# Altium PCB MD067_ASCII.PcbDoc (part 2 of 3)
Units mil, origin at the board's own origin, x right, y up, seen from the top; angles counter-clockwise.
Board outline 3650 x 4750 mil, 4 copper layers (Top Layer, GND Layer, Power Layer, Bottom Layer), stack 58.4 mil thick; 234 components, 118 nets, 586 pads, 972 vias.
Unrouted connection lines stored in the file: 42.
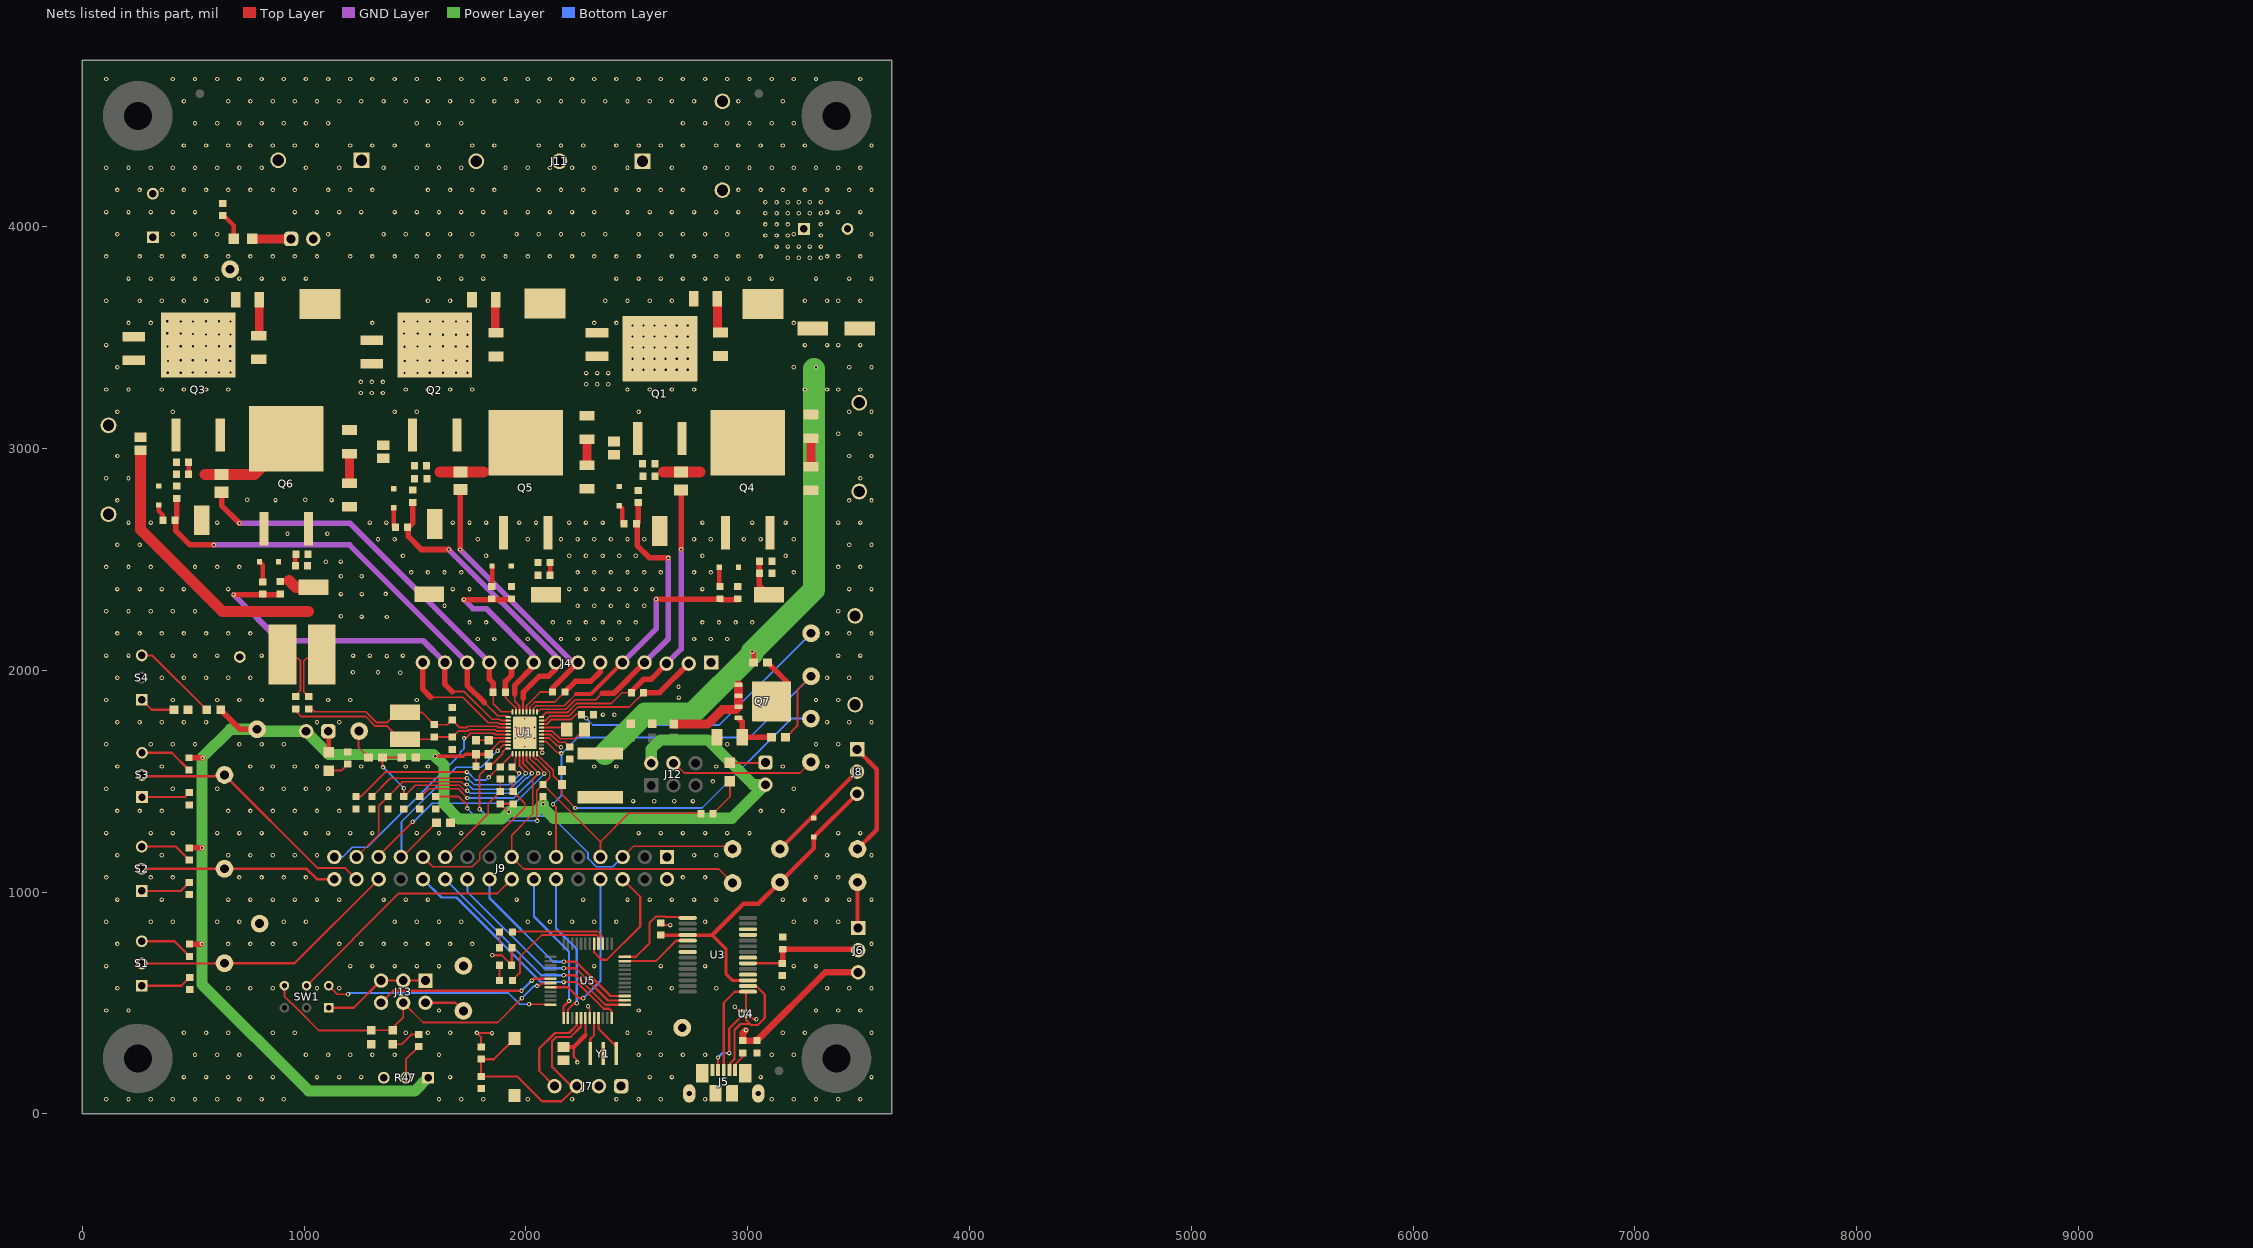
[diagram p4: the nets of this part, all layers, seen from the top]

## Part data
C1 C37: library part CMP-0006872-5, "CAP, CERM, 10 uF, 6.3 V, +/- 20%, X5R, 0603"
C2 C38: library part CMP-0085846-1, "CAP, CERM, 0.1 µF, 6.3 V,+/- 10%, X5R, 0603"
C3: library part CMP-0008374-1, "CAP, CERM, 0.47 uF, 100 V, +/- 10%, X7R, 0805"
C4: library part CMP-0007302-2, "CAP, CERM, 1 uF, 6.3 V, +/- 10%, X5R, 0603"
C5: library part CMP-0007007-5, "CAP, CERM, 10 uF, 25 V, +/- 20%, X5R, 0603"
C6: library part CMP-0009304-2, "CAP, CERM, 10 uF, 100 V, +/- 20%, X7R, 2220"
C7: library part CMP-0007470-5, "CAP, CERM, 0.1 uF, 100 V, +/- 10%, X7R, 0603"
C8 C9 C10: library part CMP-0007006-5, "CAP, CERM, 1 uF, 25 V, +/- 10%, X5R, 0603"
C11 C16 C47: library part CMP-0006815-4, "CAP, CERM, 0.1 uF, 10 V, +/- 10%, X7R, 0603"
C12 C13 C14 C24 C25 C26: library part CMP-0008756-2, "CAP CER 3900PF 100V X7R 1206"
C15 C17 C19 C27 C28 C29: library part CMP-0007441-5, "CAP, CERM, 2000 pF, 50 V, +/- 10%, X7R, 0603"
C18 C20 C44: library part CMP-0009182-2, "CAP, CERM, 4.7 uF, 100 V, +/- 10%, X7S, 1210"
C21 C22 C23: library part CMP-0007542-2, "CAP, CERM, 0.01 uF, 100 V, +/- 5%, X7R, 0805"
C30 C32: library part CMP-0006740-4, "CAP, CERM, 330 pF, 100 V, +/- 10%, X7R, 0603"
C31: library part CMP-0006998-4, "CAP, CERM, 0.01 uF, 50 V, +/- 5%, C0G/NP0, 0603"
C33: library part CMP-0011397-2, "CAP, AL, 10 uF, 80 V, +/- 20%, 2.4 ohm, SMD"
C34 C35: library part CMP-0009875-2, "CAP, AL, 390 uF, 100 V, +/- 20%, 0.026 ohm, TH"
C36: library part CMP-0006812-1, "CAP, CERM, 100 pF, 10 V, +/- 10%, X7R, 0603"
C39: library part CMP-0082630-1, "CAP, CERM, 2000 pF, 50 V,+/- 5%, C0G/NP0, 1206"
C46: library part CMP-0007498-4, "CAP, CERM, 4.7 uF, 10 V, +/- 20%, X7R, 0603"
C48: library part CMP-0006826-4, "CAP, CERM, 1000 pF, 16 V, +/- 10%, X7R, 0603"
C49: library part CMP-0007696-2, "CAP, CERM, 1 uF, 50 V, +/- 10%, X7R, 0805"
D1 D3: library part CMP-0002888-2, "LED, Green, SMD"
D2: library part CMP-0002829-3, "LED, Red, SMD"
D4: library part CMP-0028882-2, "Diode, Schottky, 40 V, 0.75 A, AEC-Q101, SOD-323"
D5 D6 D7 D8 D9 D10: library part CMP-0076911-2, "Diode, Switching, 75 V, 0.25 A, SOD-323"
D13 D14: library part CMP-0078131-2, "LED, Red, SMD"
FID1 FID2 FID3: library part CMP-0077181-1, "Fiducial mark.  There is nothing to buy or mount."
H1 H2 H3 H4: "Standoff, Hex, 1\"L #4-40 Nylon"
H5 H6 H7 H8: "Machine Screw, Round, #4-40 x 1/4, Nylon, Philips panhead"
J1 J2 J3: library part CMP-0075405-3, "Header, 100mil, 2x1, Gold, TH"
J4: library part CMP-0075428-1, "Header, 100mil, 14x1, Gold, TH"
J5: library part CMP-0055311-1, "Receptacle, USB 2.0, Micro B, 5 Position, R/A, SMT"
J6 J8: library part CMP-0002334-1, "Header, 100mil, 3x1, Gold, TH"
J7: library part CMP-0075409-2, "Header, 100mil, 4x1, Gold, TH"
J9: library part CMP-0075429-1, "Header, 100mil, 16x2, Gold, TH"
J10: library part CMP-0055527-1, "Terminal Block, 9.52mm, 2x1, R/A, TH"
J11: library part CMP-0055528-1, "Terminal Block, 9.52mm, 3x1, R/A, TH"
J12 J13: library part CMP-0075406-2, "Header, 100mil, 3x2, Gold, TH"
L1: library part CMP-0084877-1, "Inductor, Ferrite Bead, Ferrite, 3 A, 120 ohm, AEC-Q200 Grade 1, SMD"
Logo1: library part CMP-0074844-1
Logo2: library part CMP-0074838-1, "Texas Instrument Corporate Signature"
Logo3: library part CMP-0074847-1, "FCC_disclaimer"
Logo4: library part CMP-0074769-1
LOGO5 LOGO6: library part CMP-0074837-1, "IEC 61010-1 Hot Surface Warning"
NT1 NT2 NT3: library part CMP-0078142-2, "Single point connection between nets."
Q1 Q2 Q3 Q4 Q5 Q6: library part CMP-0092295-1, "MOSFET 60-V, N channel NexFET power MOSFET, single D2PAK, 1.6 mOhm 3-DDPAK/TO-263 -55 to 175"
Q7: library part CMP-0000817-1, "MOSFET, N-CH, 60 V, 50 A, DQJ0008A (VSONP-8)"
R1 R2 R3 R4 R5 R6 R11 R12 R43 R45 R46 R49 R55 R56 R57: library part CMP-0025874-4, "RES, 0, 5%, 0.1 W, AEC-Q200 Grade 0, 0603"
R7 R8 R9 R10: library part CMP-0025830-4, "RES, 5.1 k, 5%, 0.1 W, AEC-Q200 Grade 0, 0603"
R13 R14: library part CMP-0025941-5, "RES, 820, 5%, 0.1 W, 0603"
R15: library part CMP-0023463-3, "RES, 2.00 k, 0.1%, 0.1 W, 0603"
R16: library part CMP-0025925-5, "RES, 47 k, 5%, 0.1 W, 0603"
R17 R18: library part CMP-0025924-5, "RES, 470, 5%, 0.1 W, 0603"
R19 R20 R21 R23 R24 R48 R52 R53: library part CMP-0086251-1, "RES, 10.0 k, 0.05%, 0.1 W, AEC-Q200 Grade 0, 0603"
R22 R60 R75 R76 R77 R78: library part CMP-0025701-2, "RES, 10 k, 5%, 0.1 W, 0603"
R25 R26 R27 R40 R41 R42: library part CMP-0016763-3, "RES, 1.50, 1%, 0.25 W, AEC-Q200 Grade 0, 1206"
R28 R29 R30 R31 R32 R33 R34 R35 R36 R37 R38 R39: library part CMP-0025703-4, "RES, 10, 5%, 0.1 W, AEC-Q200 Grade 0, 0603"
R44: library part CMP-0015025-2, "RES, 0.001, 1%, 4 W, RES_2725"
R47: library part CMP-0001776-2, "Trimmer Potentiometer, 25kohm, 0.5W, TH"
R50: library part CMP-0085900-1, "RES, 1.00 M, 1%, 0.1 W, AEC-Q200 Grade 0, 0603"
R51: library part CMP-0023630-1, "RES, 100 k, 0.1%, 0.1 W, 0603"
R54: library part CMP-0024269-1, "RES, 47.0, 0.1%, 0.1 W, 0603"
S1 S2 S3 S4: library part CMP-0002155-2, "SWITCH TOGGLE SPDT 0.4VA 28V"
S5: library part CMP-0002196-2, "Switch, Tactile, SPST, 12 V, SMD"
SH-J1 SH-J2 SH-J3 SH-J4 SH-J5 SH-J6 SH-J7 SH-J8 SH-J10 SH-J11 SH-J12 SH-J13 SH-J14 SH-J15 SH-J16 SH-J17 SH-J18 SH-J19 SH-J20 SH-J21 SH-J22 SH-J23 SH-J24: library part CMP-0003623-3, "Shunt, 100mil, Gold plated, Black"
SW1: library part CMP-0002204-1, "Switch, DPDT, On-On, 0.4 VA, 28 V, TH"
TP1 TP10 TP14 TP30 TP40 TP41 TP42 TP43 TP44 TP45: library part CMP-0055137-1, "Test Point, Miniature, Red, TH"
TP2 TP3 TP4 TP5 TP26 TP31 TP32 TP33: library part CMP-0055139-1, "Test Point, Miniature, White, TH"
TP8 TP12 TP25: library part CMP-0055138-1, "Test Point, Miniature, Black, TH"
TP9 TP11 TP15 TP16 TP17 TP18 TP19 TP20 TP39: library part CMP-0055152-1, "Test Point, Miniature, SMT"
TP21 TP22 TP23 TP24: library part CMP-0075110-1, "1mm Uninsulated Shorting Plug, 10.16mm spacing, TH"
TP27 TP28 TP29: library part CMP-0055153-1, "Test Point, Compact, SMT"
U1: library part CMP-0095893-1, "High Speed Sensorless Trapezoidal Control 4.5 to 60 V Three-phase BLDC Gate Driver"
U3: library part CMP-0004774-1, "USB to Serial UART, SSOP28"
U4: library part CMP-0043115-3, "4-Channel ESD Protection Array for High-Speed Data Interfaces, DRY0006A (USON-6)"
U5: library part CMP-0089204-1, "CPU16 MSP430™ FRAM Microcontroller IC 16-Bit 24MHz 32KB (32K x 8) FRAM 48-LQFP (7x7)"
Y1: library part CMP-0084387-1, "Resonator, 4 MHz, 39 pF, AEC-Q200 Grade 1, SMD"
ZZ1: library part CMP-0003616-3
ZZ2: library part CMP-0077236-1
ZZ3: library part CMP-0077237-1
ZZ4: library part CMP-0077238-1

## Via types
v1: diameter 20, hole 10, Top Layer to Bottom Layer, tented both sides, 896 vias
v2: diameter 20, hole 10, Top Layer to Bottom Layer, 67 vias
v3: diameter 19.68, hole 7.87, Top Layer to Bottom Layer, 8 vias
v4: diameter 20, hole 10, Top Layer to Bottom Layer, tented top, 1 vias

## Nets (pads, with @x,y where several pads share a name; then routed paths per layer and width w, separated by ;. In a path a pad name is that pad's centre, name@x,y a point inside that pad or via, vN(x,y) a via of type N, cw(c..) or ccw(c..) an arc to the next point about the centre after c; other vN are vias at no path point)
3V3_MCU: C49.1 D4.1 J7.2 J8.2 R16.2 R17.2 R18.2 TP45.1 U5.6 | length 1100.8
  Top Layer w10: R16.2@1798,301.56 1798,346 v1(1779,365) 1846,365 v1(1847,364) ; v2(1848,715) 1890.56,715 R17.2@1935.56,670 1936.56,671 R18.2@1936.56,748 ; 2215.53,301.53 2215.53,257 2232,240.53 v1(2232,232) ; 2268,354 2268,432.52 U5.6@2268.16,432.68
  Top Layer w19.68: TP45.1@3145,1194 3285.31,1334.31 D4.1@3298,1334.31 3298,1348 J8.2@3493,1543
  Top Layer w20: C49.1@2168.94,301.53 2215.53,301.53 2268,354
3V3COM: C16.1 D4.2 J8.3 TP41.1 U3.4 U3.17 | length 1489.9
  Top Layer w15: C16.1@2607,805.44 2726.88,805.44 2727.35,805.91 2840.09,805.91 2902,744 2902,631 2931.82,601.18 U3.17@2999,601.18
  Top Layer w19.68: 2840.09,805.91 2981.19,947 3048,947 TP41.1@3145,1044 3298,1197 D4.2@3298,1247.69 3493,1442.69 J8.3@3493,1443
3V3EXT: J8.1 TP44.1 | length 521.9
  Top Layer w19.68: J8.1@3493,1643 3582,1554 3582,1281 TP44.1@3495,1194
5V_EXT: J6.1 TP43.1 | length 207.2
  Top Layer w7.87: J6.1@3495,841 J6.1@3498,838
  Top Layer w20: J6.1@3495,841 TP43.1@3495,1044
5V_USB: C11.1 J6.3 L1.1 TP42.1 U4.6 | length 742.8
  Top Layer w7.87: U4.6@3011.69,440.19 3024.87,427 v1(3039,427)
  Top Layer w29.53: v1(2992,377.56) 2977,362.56 L1.1@2977,330.56 C11.1@3042,330.56 3349.44,638 J6.3@3498,638 J6.3@3492,632
5VCC: C46.2 C47.1 J6.2 U3.20 | length 561.3
  Top Layer w10: U3.20@3001,678.82 C46.2@3155.74,678.82
  Top Layer w25: C46.2@3155.74,678.82 3157,680.08 C47.1@3157,742.17 3493.83,742.17 J6.2@3498,738
AVDD: C1.1 C2.1 J1.2 J2.2 J12.2 R7.1 R8.2 R9.2 R10.2 R19.2 R21.2 R24.2 R47.1 R52.2 TP10.1 U1.26 | length 6869.6
  Top Layer w7.87: 1726,1621 1726.5,1621.5 ; C1.1@1775,1621.5 1775.44,1621.5 R8.2@1775.44,1568 ; C2.1@1832.49,1621.5 1832.49,1628.49 1882.63,1678.63 U1.26@1920.2,1678.63 ; v1(1923,1362) 1920.44,1362 R10.2@1885,1397.44 R9.2@1943,1397.44 ; R7.1@2077,1430.71 2078,1429.71 v2(2078,1396)
  Top Layer w15: v1(1591,1612) 1591.32,1612.32 1717.32,1612.32 1726,1621 ; 1726.5,1621.5 C1.1@1775,1621.5 ; C1.1@1775.44,1621.5 C2.1@1832.49,1621.5
  Top Layer w25: R24.2@481,1605.56 541.44,1605.56 v1(542,1605) ; R21.2@482,1199.56 539.56,1199.56 v1(540,1200) ; R19.2@483,765.56 538.56,765.56 v1(539,766) ; R52.2@623.5,1822 711.5,1734 TP10.1@788,1734
  Power Layer w50: v1@540,1605 v1(540,1200) 540,584 1021,103 1499,103 R47.1@1559,163 ; v1@540,1607 667,1734 TP10.1@788,1734 797,1725 J1.2@1009,1725 1009,1723.06 1111.06,1621 1582,1621 v1(1591,1612) 1630,1573 1630,1397 1697,1330 1891,1330 v1(1923,1362) 1924.87,1363.87 2045.87,1363.87 v2(2078,1396) 2079.13,1394.87 2079.13,1378.24 2124.37,1333 2929,1333 J2.2@3080,1484 3023,1484 2821.29,1685.71 2606.71,1685.71 2565,1644 J12.2@2565,1581
BRAKE: J9.27 U1.34 | length 1028.6
  Top Layer w7.87: J9.27@1336,1158 1336,1164 v4(1489,1317) ; U1.34@2018.62,1623.51 2018.62,1601.44 2035.92,1584.14 2036.7,1584.14 2076.81,1544.03 2076.81,1534 v1(2083,1534)
  Bottom Layer w7.87: v4@1488,1317 v4(1489,1317) 1495,1317 1578,1400 1950.85,1400 2083,1532.15 v1(2083,1534)
BRAKE_SW: J9.28 S1.2 TP26.1 | length 1225.4
  Top Layer w10: S1.2@268,677.95 639.95,677.95 TP26.1@641,679 957,679 J9.28@1336,1058
BSTA: C8.2 J4.2 U1.9 | length 770.6
  Top Layer w7.87: U1.9@2069.8,1773.12 2086.8,1773.12 2106.98,1793.3 2193.11,1793.3 2234.07,1834.25 2465.81,1834.25 C8.2@2530.56,1899
  Top Layer w25: C8.2@2530.56,1899 2603,1899 J4.2@2734,2030
BSTB: C9.1 J4.6 U1.13 | length 446.1
  Top Layer w7.87: U1.13@2018.62,1812.49 2018.62,1834.56 2041.06,1857 2129.99,1857 C9.1@2175.12,1902.13
  Top Layer w25: C9.1@2175.12,1902.13 2222.99,1950 2292,1950 2335,1993 J4.6@2335,2035
BSTC: C10.1 J4.10 U1.17 | length 254
  Top Layer w7.87: C10.1@1907.56,1901 1907.56,1877 1944.18,1840.38 1944.62,1840.38 1955.63,1829.37 U1.17@1955.63,1812.49
  Top Layer w25: C10.1@1907.56,1901 1907.56,1949.56 1935,1977 J4.10@1935,2035
CPH: C3.1 U1.7 | length 117.4
  Top Layer w7.87: U1.7@2069.8,1741.62 2176.38,1741.62 C3.1@2184,1734
CPL: C3.2 U1.6 | length 226.7
  Top Layer w7.87: U1.6@2069.8,1725.87 2118.92,1725.87 2154.11,1690.69 2220.69,1690.69 C3.2@2264,1734
DACOUT/SOX/SPEED_ANA: J9.15 R3.1 TP2.1 U1.33 | length 2196.4
  Top Layer w7.87: R3.1@1522,1430.36 1526.36,1430.36 1562,1466 1694,1466 v1(1736,1424) ; U1.33@2002.87,1623.51 2002.87,1590.97 2048.81,1545.03 2048.81,1535.19 2049,1535 v1(2055,1535) 2055,1533.15 2031,1509.15 2031,1351.8 1936,1256.8 J9.15@1936,1158 1990,1104 2868.82,1104 TP2.1@2931.82,1041
  Bottom Layer w7.87: v1(1736,1424) 1945.85,1424 2055,1533.15 v1(2055,1535)
DACOUT_SPEED_ANA: J9.16 SW1.5 | length 1123.8
  Top Layer w7.87: SW1.5@1011,578 1427,994 1872,994 J9.16@1936,1058
DIR: J9.29 R6.1 U1.31 | length 1125.4
  Top Layer w7.87: J9.29@1236,1158 1336,1258 1336,1388.36 R6.1@1378,1430.36 1445.14,1497.5 1707.05,1497.5 1720.54,1484 1721.54,1485 v1(1734,1485) ; U1.31@1971.38,1623.51 1971.38,1568.68 1999.05,1541 v1(1999.05,1536)
  Bottom Layer w7.87: v1(1734,1485) 1738.85,1485 1760.85,1463 1927.85,1463 1999.05,1534.21 v1(1999.05,1536)
DIR_SW: J9.30 S3.2 TP32.1 | length 1170.4
  Top Layer w10: S3.2@269,1528 269,1521.82 634.82,1521.82 TP32.1@641,1528 1061,1108 1186,1108 J9.30@1236,1058
DM: J5.2 U3.16 U4.5 | length 595
  Top Layer w10: J5.2@2917.59,197 2921.45,200.86 2921.45,228.36 2940,246.91 2940,378.21 2967.23,405.43 3008.48,405.43 3009,405.95 ; U4.5@2992,440.19 2992,422.95 3009,405.95 ; U3.16@3001,576.46 3001,572.6 3042.48,572.6 3055.21,559.87 3055.21,559.79 3077,538 3077,432.65 3045.35,401 3013.95,401 3009,405.95
DP: J5.3 U3.15 U4.2 | length 524.4
  Top Layer w10: J5.3@2892,197 2892,501 2941.87,550.87 U3.15@3001,550.87 2992,541.87 U4.2@2992,463.81
DRVOFF: J9.31 U1.24 | length 1050
  Top Layer w7.87: v1(1721,1693) 1728.41,1693 1751.41,1715.99 1856.09,1715.99 1861.95,1710.13 U1.24@1920.2,1710.13
  Bottom Layer w7.87: J9.31@1136,1158 1173.36,1158 1217.65,1202.29 1285.29,1202.29 1704.19,1621.19 1704.19,1630.03 1721,1646.85 v1(1721,1693)
DRVOFF_SW: J9.32 S2.2 TP31.1 | length 887.5
  Top Layer w12: S2.2@268,1105 TP31.1@641,1105 1011,1105 1058,1058 J9.32@1136,1058
DVDD: C4.1 TP1.1 U1.36 | length 1545
  Top Layer w7.87: U1.36@2050.12,1623.51 2050.12,1621.04 2122.72,1548.43 2122.72,1525.24 C4.1@2163,1484.96 2163,1439 v2(2223,1379)
  Bottom Layer w7.87: v2(2223,1379) 2794,1379 3197,1782 TP1.1@3285,1782
EXT_CLK: R1.1 R46.2 R50.2 U1.32 | length 1064.1
  Top Layer w7.87: v1(1356,1562) 1353.5,1564.5 R46.2@1353.5,1607 R50.2@1440.5,1607 ; v1(1450,1468) R1.1@1450,1430.36 1501.39,1481.75 1700.52,1481.75 1725.27,1457 v1(1736,1457) ; U1.32@1987.13,1623.51 1987.13,1578.77 2020.87,1545.03 2020.87,1536.13 2021,1536 v1(2027,1536)
  Bottom Layer w7.87: v1(1356,1562) v1(1450,1468) ; v1(1736,1457) 1748,1445 1932.12,1445 2001.31,1514.19 2008.09,1514.19 2027,1533.1 v1(2027,1536)
FGOUT: J9.5 R8.1 TP4.1 U1.28 | length 1649.1
  Top Layer w7.87: v1(1791,1373) 1791,1528.44 R8.1@1830.56,1568 1839.26,1568 1894.81,1623.55 1894.81,1632.25 1909.69,1647.13 U1.28@1920.2,1647.13 ; J9.5@2436,1158 2485,1207 2918.82,1207 TP4.1@2931.82,1194
  Bottom Layer w7.87: v1(1791,1373) 1825,1339 2028.15,1339 2031.97,1342.81 2113.83,1342.81 2280.29,1176.35 2280.29,1151.07 2317.65,1113.71 2391.71,1113.71 J9.5@2436,1158
GCTRL: J9.11 R56.1 TP5.1 U1.3 | length 2197.2
  Top Layer w7.87: U1.3@2069.8,1678.63 2091.88,1678.63 2141.51,1629 2159,1629 2160,1628 v1(2160,1625) ; v1(2122,1396) 2136,1382 J9.11@2136,1158 ; R56.1@3170.5,1698 3173,1698 3224,1749 3224,1911 TP5.1@3286,1973
  Bottom Layer w7.87: v1(2122,1396) 2160,1434 v1(2160,1625) 2160.85,1625 2232.85,1697 3010,1697 TP5.1@3286,1973
GHA: J4.4 R28.1 R31.1 U1.11 | length 1447.2
  Top Layer w7.87: U1.11@2050.12,1812.49 2053.49,1812.49 2065.8,1824.8 2180.07,1824.8 2222.27,1867 2315,1867 2344,1896
  Top Layer w25: 2344,1896 2396,1896 J4.4@2535,2035 ; R28.1@2505.94,2751.69 2505.94,2664.45 2501.5,2660 2501.5,2563.5 2558.19,2506.81 v1(2642,2506.81)
  GND Layer w25: J4.4@2535,2035 2642,2142 v1(2642,2506.81)
GHA_FET: C15.1 D5.2 Q1.1 R22.2 R28.2 TP15.1
GHB: J4.8 R29.1 R32.1 U1.15 | length 1395.7
  Top Layer w7.87: U1.15@1987.13,1812.49 1987.13,1875
  Top Layer w19.68: J4.8@2118.75,2031.75 J4.8@2135,2031.75
  Top Layer w25: R29.1@1490,2753.5 1490,2664.18 1469.95,2644.13 1469.95,2602.41 1527.89,2544.47 v1(1651.87,2544.47) ; 1987.13,1875 1987.13,1900.13 2061,1974 2102,1974 2135,2007 J4.8@2135,2031.75
  GND Layer w25: v1(1651.87,2544.47) 2135,2061.34 J4.8@2135,2035
GHB_FET: C17.1 D6.2 Q2.1 R29.2 R60.2 TP16.1
GHC: J4.12 R30.1 R33.1 U1.19 | length 2050.4
  Top Layer w7.87: 1813,1854 1872.27,1794.73 1914.33,1794.73 U1.19@1920.2,1788.87
  Top Layer w25: R30.1@425,2771.02 425,2679.47 421.92,2676.39 421.92,2628.08 485,2565 v1(592.9,2565) ; J4.12@1735,2035 1735,1932 1813,1854
  GND Layer w25: v1(592.9,2565) 1205,2565 J4.12@1735,2035
GHC_FET: C19.1 D7.2 Q3.1 R30.2 R75.2 TP17.1
GLA: J4.5 R34.1 R37.1 U1.12 | length 1218.5
  Top Layer w7.87: U1.12@2034.37,1812.49 2034.37,1828.04 2046.88,1840.54 2173.54,1840.54 2226,1893
  Top Layer w19.68: 2226,1893 2293,1893 J4.5@2435,2035
  Top Layer w25: v1(2587,2320) 2873.5,2320 2875,2318.5 R34.1@2955,2318.5
  GND Layer w25: J4.5@2435,2035 2587,2187 v1(2587,2320)
GLA_FET: C27.1 D8.2 Q4.1 R34.2 R76.2 TP18.1 | length 170.4
  Top Layer w25: R76.2@3053.44,2492 3052.44,2491 3052.44,2382.18 TP18.1@3095,2339.62
GLB: J4.9 R35.1 R38.1 U1.16 | length 930
  Top Layer w7.87: 1950,1893 1950,1860 1971.38,1838.62 U1.16@1971.38,1812.49
  Top Layer w25: v1(1720.5,2318.5) R35.1@1935,2318.5 ; 1950,1893 1950,1933 2035,2018 J4.9@2035,2035
  GND Layer w25: v1(1720.5,2318.5) 1761.01,2278 1821,2278 2035,2064 J4.9@2035,2035
GLB_FET: C28.1 D9.2 Q5.1 R35.2 R77.2 TP19.1
GLC: J4.13 R36.1 R39.1 U1.20 | length 1742.7
  Top Layer w7.87: 1667,1904 1722,1904 1847.02,1778.98 1882.18,1778.98 1888.04,1773.12 U1.20@1920.2,1773.12
  Top Layer w25: v1(682,2341) 810.41,2341 812.41,2339 813.96,2340.55 R36.1@891.77,2340.55 ; J4.13@1635,2035 1635,1936 1667,1904
  GND Layer w25: v1(682,2341) 890,2133 1537,2133 J4.13@1635,2035
GLC_FET: C29.1 D10.2 Q6.1 R36.2 R78.2 TP20.1 | length 176.7
  Top Layer w20: C29.1@960.44,2471 960.44,2522.17 R78.2@962.26,2523.99
  Top Layer w50: 931.5,2405.62 963.11,2374.02 TP20.1@1041.38,2374.02
GND: C1.2 C2.2 C4.2 C5.2 C6.2 C7.2 C11.2 C16.2 C18.2 C20.2 C30.1 C32.2 C33.2 C34.2 C35.2 C36.2 C37.2 C38.2 C39.2 C44.2 C46.1 C47.2 C48.2 C49.2 J4.1 J5.5 J5.6 J5.7 J5.8 J5.9 J5.10 J5.11 J7.1 J9.1 J9.2 J10.2 R1.2 R2.2 R3.2 R4.2 R5.2 R6.2 R13.1 R15.1 R20.1 R23.1 R44.1 R45.2 R47.3 R48.1 R50.1 R51.1 R53.1 S5.2 TP8.1 TP12.1 TP21.1 TP21.2 TP22.1 TP22.2 TP23.1 TP23.2 TP24.1 TP24.2 TP25.1 U1.1 U1.4 U1.25 U1.37 U3.7 U3.18 U3.21 U3.25 U3.26 U4.3 U5.7 Y1.2 | length 731.5
  Top Layer w7.87: C1.2@1775,1684.5 C2.2@1832.49,1684.5 1842.37,1694.38 U1.25@1920.2,1694.38 ; U1.1@2069.8,1647.13 2069.8,1627.2 2071.61,1629 v1(2074,1629) ; U1.4@2069.8,1694.38 2105.88,1694.38 2141.06,1659.19 2157,1659.19 2158,1658.19 v1(2158,1653) ; v2(2280,485) 2287.84,477.16 U5.7@2287.84,432.68 ; C16.2@2607,860.56 2616.22,851.33 v1(2650.79,851.33) ; v1(2941.87,483) 2961.06,463.81 U4.3@2972.32,463.81
  Top Layer w8: R44.1@856.42,2080 R44.1@902,2080 ; R44.1@902.42,2072 920.42,2054 971.12,2054 983,2042.12 983,1909 963,1889 R45.2@963,1881.56
  other v1: 108,66 208,66 308,66 408,66 508,66 608,66 708,66 808,66 908,66 1608,66 1708,66 1808,66 2008,66 2208,66 2408,66 2508,66 2608,66 2808,66 3108,66 3208,66 3308,66 3408,66 3508,66 458,166 558,166 658,166 758,166 858,166 1058,166 1158,166 1258,166 1658,166 2558,166 2658,166 3058,166 3558,166 508,266 608,266 708,266 1008,266 1108,266 1208,266 1308,266 1408,266 1608,266 2508,266 2608,266 2708,266 2808,266 3108,266 3208,266 458,366 558,366 658,366 858,366 958,366 1458,366 1558,366 1658,366 2458,366 2558,366 3158,366 3258,366 3558,366 108,466 208,466 1608,466 2508,466 3308,466 3408,466 3508,466 158,566 658,566 758,566 858,566 1058,566 1158,566 2558,566 2658,566 2858,566 3158,566 3358,566 3458,566 3558,566 108,666 1208,666 1308,666 1408,666 1508,666 1608,666 2308,666 2608,666 2808,666 3208,666 3308,666 158,766 658,766 758,766 858,766 958,766 1158,766 1258,766 1358,766 1458,766 1558,766 1658,766 1758,766 3558,766 108,866 308,866 408,866 608,866 708,866 908,866 1008,866 1408,866 1508,866 1608,866 1708,866 2008,866 2108,866 2208,866 2308,866 2408,866 2808,866 3208,866 3308,866 3408,866 158,966 358,966 658,966 758,966 858,966 958,966 1058,966 1158,966 1358,966 1458,966 1558,966 1958,966 2258,966 2458,966 2558,966 2658,966 2758,966 2858,966 3158,966 3258,966 3358,966 3458,966 3558,966 108,1066 308,1066 408,1066 708,1066 808,1066 908,1066 1008,1066 2708,1066 2808,1066 3308,1066 3408,1066 158,1166 358,1166 658,1166 758,1166 858,1166 958,1166 1058,1166 2758,1166 2858,1166 3358,1166 3558,1166 108,1266 308,1266 408,1266 608,1266 708,1266 808,1266 1008,1266 1108,1266 1208,1266 1308,1266 1508,1266 1608,1266 1708,1266 1808,1266 2008,1266 2108,1266 2508,1266 2608,1266 2708,1266 2808,1266 2908,1266 3008,1266 3408,1266 3508,1266 158,1366 258,1366 358,1366 658,1366 758,1366 858,1366 958,1366 1058,1366 1158,1366 3058,1366 3158,1366 2483.12,1410 2579,1409.58 2669.11,1409.58 2753,1410 108,1466 408,1466 608,1466 808,1466 908,1466 1008,1466 1108,1466 3208,1466 2842,1499 158,1566 358,1566 758,1566 858,1566 958,1566 1058,1566 1258,1566 1458,1566 1558,1566 2858,1566 3158,1566 3358,1566 108,1666 308,1666 408,1666 508,1666 708,1666 808,1666 908,1666 2908,1666 3308,1666 3408,1666 158,1766 258,1766 358,1766 458,1766 558,1766 1058,1766 1158,1766 3358,1766 3458,1766 3558,1766 2399,1799 2347,1800 108,1866 408,1866 608,1866 708,1866 808,1866 1108,1866 1208,1866 1508,1866 3308,1866 3408,1866 2688.55,1877 2688,1926 158,1966 358,1966 458,1966 558,1966 658,1966 758,1966 3358,1966 3458,1966 3558,1966 108,2066 208,2066 408,2066 508,2066 608,2066 808,2066 3408,2066 3508,2066 158,2166 258,2166 358,2166 458,2166 558,2166 658,2166 758,2166 3358,2166 3458,2166 3558,2166 108,2266 208,2266 308,2266 408,2266 508,2266 3408,2266 158,2366 258,2366 358,2366 458,2366 658,2366 3458,2366 3558,2366 108,2466 208,2466 308,2466 508,2466 608,2466 708,2466 3408,2466 3508,2466 158,2566 258,2566 3458,2566 3558,2566 208,2666 308,2666 608,2666 3408,2666 3508,2666 158,2766 3458,2766 3558,2766 108,2866 208,2866 3508,2866 158,2966 3458,2966 3558,2966 3408,3066 3508,3066 158,3166 3458,3166 3558,3166 1255,3250 1305,3250 1355,3250 108,3266 208,3266 3408,3266 3508,3266 2271.66,3290 2321.66,3290 2371.66,3290 1255,3300 1305,3300 1355,3300 2271.66,3340 2321.66,3340 2371.66,3340 158,3366 3458,3366 3558,3366 108,3466 3408,3466 3508,3466 108,3666 3408,3666 3508,3666 3458,3766 3558,3766 108,3866 3408,3866 3508,3866 158,3966 3558,3966 108,4066 208,4066 308,4066 408,4066 508,4066 3408,4066 3508,4066 158,4166 258,4166 358,4166 458,4166 558,4166 658,4166 758,4166 858,4166 958,4166 2958,4166 3058,4166 3158,4166 3258,4166 3358,4166 3458,4166 3558,4166 108,4266 208,4266 308,4266 408,4266 508,4266 608,4266 708,4266 808,4266 1008,4266 1508,4266 2808,4266 2908,4266 3008,4266 3108,4266 3208,4266 3308,4266 3408,4266 3508,4266 458,4366 558,4366 658,4366 758,4366 858,4366 958,4366 1058,4366 1558,4366 2858,4366 2958,4366 3058,4366 3158,4366 3258,4366 3558,4366 508,4466 608,4466 708,4466 808,4466 908,4466 1008,4466 1108,4466 1508,4466 1608,4466 1708,4466 2708,4466 2808,4466 2908,4466 3008,4466 3108,4466 3208,4466 458,4566 658,4566 758,4566 858,4566 958,4566 1058,4566 1158,4566 1258,4566 1358,4566 1458,4566 1558,4566 1658,4566 1758,4566 1858,4566 1958,4566 2058,4566 2158,4566 2258,4566 2358,4566 2458,4566 2558,4566 2658,4566 2758,4566 2958,4566 3158,4566 108,4666 408,4666 508,4666 608,4666 708,4666 808,4666 908,4666 1008,4666 1108,4666 1208,4666 1308,4666 1408,4666 1508,4666 1608,4666 1708,4666 1808,4666 1908,4666 2008,4666 2108,4666 2208,4666 2308,4666 2408,4666 2508,4666 2608,4666 2708,4666 2808,4666 2908,4666 3008,4666 3108,4666 3208,4666 3308,4666 3508,4666
  other v3: 1995,1655.01 1951.69,1693.39 1995,1693.39 2038.31,1693.39 1951.69,1742.61 1995,1742.61 2038.31,1742.61 1995,1780.99
GVDD: C5.1 TP40.1 U1.8 | length 1442.3
  Top Layer w7.87: U1.8@2069.8,1757.37 2093.32,1757.37 2113.5,1777.55 2201.64,1777.55 2226.08,1802 C5.1@2258.98,1802 ; C5.1@2250.44,1800 2257,1800 v1@2273.63,1783.37 ; v1(2271.94,1783.37) v1@2273.63,1783.37 ; v1@2277,1780 v1@2273.63,1783.37
  Bottom Layer w7.87: v1(2271.94,1783.37) 2302.31,1753 2872,1753 TP40.1@3286,2167
ID: J5.4 U4.4 | length 305.6
  Top Layer w10: v1(2866,254) 2866,197.41 J5.4@2866.41,197 ; v1(2917,274) 2917,384.87 U4.4@2972.32,440.19
  Bottom Layer w10: v1(2866,254) 2886,274 v1(2917,274)
LSS: C21.2 C22.2 C23.2 C27.2 C28.2 C29.2 J4.14 Q4.3 Q5.3 Q6.3 R40.1 R41.1 R42.1 R43.2 R44.2 R76.1 R77.1 R78.1 TP9.1 U1.21 | length 2148.6
  Top Layer w7.87: R43.2@1020,1881.56 998.81,1902.75 998.81,2042.24 1010.57,2054 1061.58,2054 R44.2@1079.58,2072 ; 1571,1878 1715,1878 1829.76,1763.24 1875.65,1763.24 1881.52,1757.37 U1.21@1920.2,1757.37
  Top Layer w19.68: R77.1@2109.56,2429 C28.2@2109.56,2486
  Top Layer w25: J4.14@1535,2035 1535,1914 1571,1878
  Top Layer w50: C23.2@261.85,2981.65 261.85,2635.15 631.94,2265.06 1020,2265.06
  other v1: 1433.27,1989 1220,1991 1333,1991 1372.42,2064 1220.5,2066 1295.5,2066 1445.5,2066 1783,2141 1858,2141 2008,2141 2158,2141 2233,2141 2308,2141 2383,2141 2458,2141 2758,2141 2833,2141 2908,2141 1745.5,2216 1820.5,2216 2120.5,2216 2195.5,2216 2270.5,2216 2345.5,2216 2420.5,2216 2495.5,2216 2795.5,2216 2870.5,2216 2945.5,2216 3020.5,2216 1373,2240.1 1259,2242 1165.82,2244 1633,2291 2233,2291 2308,2291 2383,2291 2458,2291 2533,2291 1165.82,2343.44 1260,2343.44 1367,2344.49 1670.5,2366 1745.5,2366 2195.5,2366 2270.5,2366 2345.5,2366 2420.5,2366 2495.5,2366 2570.5,2366 2795.5,2366 1165.82,2424 1259,2424 1483,2441 1558,2441 1633,2441 1708,2441 2233,2441 2308,2441 2383,2441 2458,2441 2533,2441 2608,2441 2758,2441 2833,2441 3208,2441 1097,2489 1165,2489.83 1445.5,2516 1820.5,2516 2195.5,2516 2270.5,2516 2345.5,2516 2420.5,2516 2495.5,2516 2795.5,2516 3170.5,2516 1333,2591 1408,2591 1783,2591 2008,2591 2158,2591 2233,2591 2308,2591 2383,2591 2458,2591 2533,2591 2758,2591 2833,2591 2983,2591 3058,2591 3208,2591 1295.5,2666 1370.5,2666 1670.5,2666 1745.5,2666 1820.5,2666 1970.5,2666 2045.5,2666 2195.5,2666 2270.5,2666 2345.5,2666 2795.5,2666 3020.5,2666 3170.5,2666 871,2767.52 1124,2767.52 744,2769 1004.91,2769
  other v2: 925,2616 1105,2616
MCX_SCL: J9.23 R9.1 R11.1 | length 757.9
  Top Layer w7.87: J9.23@1536,1158 1580.29,1113.71 1758.71,1113.71 1791.71,1146.71 1791.71,1176.35 1995,1379.64 1995,1400.56 R9.1@1943,1452.56 1937.29,1458.27 R11.1@1937.29,1508.73
MCX_SDA: J9.21 R10.1 R12.1 | length 477.5
  Top Layer w7.87: J9.21@1636,1181.36 J9.21@1636,1158 1830.56,1352.56 1830.56,1398.12 R10.1@1885,1452.56 1884.29,1453.27 R12.1@1884.29,1508.73
MSP_A1_P1.1: J9.12 U5.2 | length 686.2
  Top Layer w10: U5.2@2189.42,432.68 2190.32,433.58 2190.32,471.06 2218.27,499 v1(2228.79,499)
  Bottom Layer w10: J9.12@2136,1058 2136,836 2228.79,743.21 v1(2228.79,499)
MSP_A2_P1.2: J9.14 U5.1 | length 711.6
  Top Layer w10: U5.1@2169.73,432.68 2169.73,484.17 v1(2194.56,509)
  Bottom Layer w10: J9.14@2028.73,1050.73 J9.14@2036,1058 2036,890 2194.56,731.44 v1(2194.56,509)
MSP_A3_P1.3: SW1.4 U5.48 | length 1040.4
  Top Layer w7.87: SW1.4@1111,578 1150,539 v1(1198,539) ; v1(2014,494) 2014.3,493.7 2108.71,493.7 U5.48@2109.77,492.64
  Top Layer w10: U5.48@2109.77,492.64 U5.48@2110.68,491.73
  Bottom Layer w7.87: v1(1198,539) 1204.08,545.08 1920.92,545.08 1972,494 v1(2014,494)
MSP_CLK_P4.5: J9.20 U5.14 | length 968.5
  Top Layer w10: v1(2171,656) 2225,656 2369.58,511.42 U5.14@2445.32,511.42
  Bottom Layer w10: J9.20@1736,1058 1736,1002 2082,656 v1(2171,656)
MSP_FGOUT_P2.1: J9.6 U5.29 | length 568
  Top Layer w10: U5.29@2307.53,767.32 2307.53,728.47 2341,695 2365,695 2515,845 2515,979 J9.6@2436,1058
MSP_LED0_P2.2: D13.2 U5.28 | length 549.2
  Top Layer w7.87: D13.2@1939.53,602.05 1973,635.52 1973,707.47 2072.22,806.69 2317.18,806.69 2325.24,798.63 2325.24,767.32 U5.28@2327.21,767.32
MSP_LED1_P2.2: D14.2 U5.27 | length 450.2
  Top Layer w7.87: D14.2@1940.53,820 1942.97,822.44 2323.71,822.44 2344.93,801.22 2344.93,769.29 U5.27@2346.9,767.32
  Top Layer w10: U5.27@2346.9,767.32 U5.27@2347.8,768.23
MSP_nFAULT_P3.3: J9.8 U5.44 | length 737.1
  Top Layer w10: U5.44@2110.68,570.47 2189.66,570.47 2239.14,521 v1(2258,521)
  Bottom Layer w10: v1(2258,521) 2336,599 J9.8@2336,1058
MSP_RX_P4.3: U3.5 U5.23 | length 320
  Top Layer w10: U5.23@2445.32,688.58 2585.04,688.58 2676.77,780.32 U3.5@2727.35,780.32
MSP_SBWTCK: J7.4 U5.4 | length 444.5
  Top Layer w10: J7.4@2129,125 2060,194 2060,294.28 2130.6,364.87 2193.87,364.87 2228.79,399.79 U5.4@2228.79,432.68 U5.4@2227.88,431.77
MSP_SBWTDIO/nRST: C48.1 J7.3 R16.1 S5.1 U5.5 | length 1230.8
  Top Layer w10: S5.1@1948,338.95 1855.49,246.44 R16.1@1798,246.44 C48.1@1798,168.56 1960.44,168.56 2072,57 2161,57 J7.3@2229,125 2205,125 2118,212 2118,327 2138,347 2202,347 2248.47,393.47 U5.5@2248.47,432.68
MSP_SIMO/SDA_P4.6: J9.22 U5.13 | length 1043.9
  Top Layer w10: v1(2170.47,625) 2225,625 2358.27,491.73 U5.13@2445.32,491.73
  Bottom Layer w10: J9.22@1636,1058 2069,625 v1(2170.47,625)
MSP_SOMI/SCL_P4.7: J9.24 U5.12 | length 1127.4
  Top Layer w10: v1(2169.73,594) 2230.72,594 2350.86,473.86 2375.93,473.86 2386.27,463.52 U5.12@2386.27,432.68
  Bottom Layer w10: J9.24@1536,1058 1619,975 1687,975 2068,594 v1(2169.73,594)
MSP_STE_P4.4: J9.18 U5.15 | length 877.4
  Top Layer w10: v1(2170.47,686) 2226,686 2380.9,531.1 U5.15@2445.32,531.1
  Bottom Layer w10: J9.18@1836,1058 1836,973 2123,686 v1(2170.47,686)
MSP_TB0.1: J13.6 U5.42 | length 808.8
  Top Layer w10: J13.6@1347,500.79 1401.21,555 v1(1980,555) ; v1(2026,601) 2033.94,608.94 2109.77,608.94 U5.42@2110.68,609.84
  Bottom Layer w10: v1(1980,555) v1(2026,601)
MSP_TX_P4.2: U3.1 U5.24 | length 415
  Top Layer w10: U5.24@2445.32,708.27 2495.68,708.27 2557,769.59 2557,861.25 2584.94,889.18 2629.06,889.18 2630.25,888 2724.89,888 U3.1@2729.35,883.54
MSP_XIN_P2.7: U5.8 Y1.1 | length 168
  Top Layer w10: Y1.1@2289.94,272 2289.94,337.42 2307.53,355 U5.8@2307.53,432.68
MSP_XOUT_P2.6: U5.9 Y1.3 | length 194.2
  Top Layer w10: U5.9@2327.21,432.68 2327.21,383.79 2408.06,302.94 Y1.3@2408.06,272
NetC12_2: C12.2 R25.2 | length 152.4
  Top Layer w39.37: R25.2@2863.43,3673.85 2863.43,3540.75 C12.2@2877.09,3527.09
NetC13_2: C13.2 R26.2 | length 146.2
  Top Layer w39.37: R26.2@1862.09,3670 1862.09,3527.91 C13.2@1865,3525
NetC14_2: C14.2 R27.2 | length 158.8
  Top Layer w39.37: C14.2@795,3512.09 797.09,3514.17 R27.2@797.09,3670
NetC24_2: C24.2 R41.2 | length 109.9
  Top Layer w39.37: R41.2@2275,2927.97 C24.2@2275,3037.91
NetC25_2: C25.2 R42.2 | length 125.8
  Top Layer w39.37: R42.2@1205,2847.09 C25.2@1205,2972.91
NetC26_2: C26.2 R40.2 | length 120.8
  Top Layer w39.37: R40.2@3285,2922.09 C26.2@3285,3042.91
NetC39_1: C39.1 Q7.4 R56.2 | length 224.7
  Top Layer w25: Q7.4@2962.64,1782.54 2960.46,1782.54 2975.91,1767.09 C39.1@2975.91,1698 R56.2@3107.5,1698
NetD1_1: D1.1 J1.1 | length 95.1
  Top Layer w20: J1.1@1109,1725 1110,1724 D1.1@1110,1630.34
NetD1_2: D1.2 R13.2 | length 98.2
  Top Layer w7.87: D1.2@1110,1547.66 1166.5,1547.66 R13.2@1196,1577.16
NetD2_1: D2.1 J2.1 | length 160.7
  Top Layer w7.87: D2.1@2920,1582.34 3078.34,1582.34 J2.1@3080,1584
NetD2_2: D2.2 R14.2 | length 178.3
  Top Layer w7.87: R14.2@2843.56,1353 2920,1429.44 D2.2@2920,1499.66
NetD3_1: D3.1 J3.1 | length 175
  Top Layer w39.37: D3.1@765.98,3945 J3.1@941,3945
NetD3_2: D3.2 R15.2 | length 128.5
  Top Layer w19.68: R15.2@633,4049.44 638.56,4049.44 683.31,4004.69 D3.2@683.31,3945
NetD5_1: D5.1 R31.2 | length 84.2
  Top Layer w20: D5.1@2421.3,2742.13 2435.08,2728.35 R31.2@2435.08,2663.66
NetD6_1: D6.1 R32.2 | length 89.6
  Top Layer w20: D6.1@1403.58,2732.28 1403.58,2647.5 R32.2@1406.95,2644.13
NetD7_1: D7.1 R33.2 | length 75.8
  Top Layer w20: D7.1@344.69,2744.69 344.69,2718.31 362.87,2700.13 R33.2@362.87,2676.39
NetD8_1: D8.1 R37.2 | length 84.9
  Top Layer w20: D8.1@2871.69,2465 2871.69,2384.8 R37.2@2875,2381.5
NetD9_1: D9.1 R38.2 | length 91
  Top Layer w20: R38.2@1845,2380 1847.49,2382.49 D9.1@1847.49,2470
NetD10_1: D10.1 R39.2 | length 93.3
  Top Layer w20: D10.1@798.27,2489.83 813.03,2475.07 R39.2@813.03,2402.62
NetD13_1: D13.1 R17.1 | length 68
  Top Layer w7.87: D13.1@1880.47,602.05 R17.1@1880.47,669.97
NetD14_1: D14.1 R18.1 | length 72
  Top Layer w7.87: R18.1@1881.44,748 D14.1@1881.44,819.97
NetJ5_1: J5.1 L1.2 | length 92.4
  Top Layer w7.87: J5.1@2943.18,197 2943.18,224.18 2977,258 L1.2@2977,275.44
NetJ12_4: J12.4 TP30.1 | length 658.8
  Top Layer w7.87: J12.4@2665,1581 2670.36,1581 2714.65,1536.71 3235.71,1536.71 TP30.1@3285,1586
NetJ13_2: J13.2 TP33.1 | length 186.2
  Top Layer w10: J13.2@1547,500.79 1681.21,500.79 TP33.1@1718,464
NetQ7_1: Q7.1 Q7.2 Q7.3 R57.1 | length 423.2
  Top Layer w40: R57.1@2667,1757.37 2819.67,1757.37 2885.22,1822.91 2945.91,1822.91 Q7.3@2958,1835 Q7.2@2958,1885 Q7.1@2958,1935
NetQ7_5: Q7.5 Q7.6 Q7.7 Q7.8 Q7.9@3107.61,1860 R55.1 | length 186.7
  Top Layer w25: R55.1@3089.5,2035 3178.08,1946.42 Q7.8@3178.08,1935 Q7.7@3178.08,1885
NetR19_1: R19.1 S1.3 | length 243
  Top Layer w10: S1.3@268,777.95 415.49,777.95 R19.1@483,710.44
NetR20_2: R20.2 S1.1 | length 231.6
  Top Layer w10: S1.1@268,577.95 446.39,577.95 R20.2@484,615.56
NetR21_1: R21.1 S2.3 | length 239.1
  Top Layer w10: S2.3@268,1205 421.44,1205 R21.1@482,1144.44
NetR23_2: R23.2 S2.1 | length 230
  Top Layer w10: S2.1@268,1005 443.44,1005 R23.2@482,1043.56
NetR24_1: R24.1 S3.3 | length 244.1
  Top Layer w10: S3.3@269,1628 403.44,1628 R24.1@481,1550.44
NetR46_1: R46.1 TP3.1 | length 139
  Top Layer w7.87: TP3.1@1248,1725.87 1245,1722.87 1245,1652.5 R46.1@1290.5,1607
NetR47_2: R47.2 R49.2 | length 163.8
  Top Layer w7.87: R47.2@1459,163 1459,246.17 R49.2@1516,303.17
NetR48_2: R48.2 S3.1 | length 221.5
  Top Layer w10: S3.1@269,1428 461.44,1428 R48.2@482,1448.56
NetR49_1: R49.1 R54.2 | length 134.6
  Top Layer w7.87: R54.2@1400,313.5 1440.5,313.5 1485.29,358.29 R49.1@1516,358.29
NetR52_1: R52.1 S4.3 | length 394
  Top Layer w10: S4.3@268,2067 315.5,2067 R52.1@560.5,1822
NetR53_2: R53.2 S4.1 | length 164.1
  Top Layer w10: S4.1@268,1867 313,1822 R53.2@413.5,1822
nFAULT: J9.7 R5.1 R7.2 R14.1 U1.35 | length 1814.2
  Top Layer w7.87: R5.1@1594,1430.36 1697.64,1430.36 1735,1393 v1(1735,1377) ; U1.35@2034.37,1623.51 2034.37,1607.96 2042.44,1599.89 2047.96,1599.89 2106.98,1540.87 2106.98,1515.8 R7.2@2077,1485.83 ; v1(2051,1321) 2048.46,1323.54 2048.46,1457.28 R7.2@2077,1485.83 ; J9.7@2336,1158 2336,1226.83 ; R14.1@2788.44,1353 2786.44,1355 2464.17,1355 2336,1226.83 ; R7.2@2077,1485.83 2336,1226.83
  Bottom Layer w7.87: v1(1735,1377) 1791,1321 v1(2051,1321)
OUTA: C12.1 C15.2 C26.1 J11.1 NT1.2 Q1.3 Q4.4 R22.1 TP27.1 | length 164.8
  Top Layer w50: 2619.68,2893.5 NT1.2@2700,2893.5 2784.46,2893.5
  other v1: 2808,3766 2908,3766 3008,3766 3108,3766 2658,3866 2758,3866 2858,3866 2958,3866 3058,3866 2508,3966 2608,3966 2708,3966 2808,3966 2908,3966 2458,4066 2558,4066 2658,4066 2758,4066 2858,4066 2408,4166 2508,4166 2608,4166 2708,4166 2458,4266 2658,4266 2408,4366 2508,4366 2608,4366 2708,4366
OUTB: C13.1 C17.2 C24.1 J11.2 NT2.2 Q2.3 Q5.4 R60.1 TP28.1 | length 194.9
  Top Layer w20: NT2.2@1704.76,2894.33 NT2.2@1715.47,2894.33
  Top Layer w50: 1613.18,2894.33 NT2.2@1704.76,2894.33 ; NT2.2@1715.47,2894.33 1808.12,2894.33
  other v1: 1808,3866 1908,3866 2008,3866 2108,3866 2208,3866 2308,3866 2408,3866 2508,3866 1958,3966 2058,3966 2158,3966 2258,3966 2358,3966 2008,4066 2108,4066 2208,4066 2308,4066 2058,4166 2158,4166 2258,4166 2008,4266 2108,4266 2208,4266 2308,4266 2058,4366 2158,4366 2258,4366
OUTC: C14.1 C19.2 C25.1 J11.3 NT3.2 Q3.3 Q6.4 R75.1 TP29.1 | length 479.3
  Top Layer w20: C19.2@479.56,2884 R75.1@479.56,2937
  Top Layer w50: 552.93,2882.52 NT3.2@627.77,2882.52 777.01,2882.52 Q6.4@920,3025.51
  other v1: 1208,3866 1308,3866 1408,3866 1508,3866 1608,3866 1708,3866 1358,3966 1458,3966 1558,3966 1658,3966 1758,3966 1408,4066 1508,4066 1608,4066 1708,4066 1808,4066 1908,4066 1558,4166 1658,4166 1758,4166 1858,4166 1608,4266 1708,4266 1908,4266 1758,4366 1858,4366
POT: C36.1 J13.4 R54.1 SW1.6 U5.43 | length 1519.2
  Top Layer w7.87: SW1.6@911,578 911,531 977.54,464.46 977.54,464.14 1065.77,375.9 1302.65,375.9 C36.1@1303.24,376.5 1398.82,376.5 1399.41,375.9 R54.1@1400,376.5 1400,388 1447,435 J13.4@1447,500.79 1535.79,412 1873,412 v1(1982,521) ; v1(2050,577) 2060.12,577 2071.31,588.19 2108.71,588.19 U5.43@2110.68,590.16
  Bottom Layer w7.87: v1(1982,521) 2038,577 v1(2050,577)
PVDD: C6.1 C7.1 C18.1 C20.1 C21.1 C22.1 C23.1 C33.1 C34.1 C35.1 C44.1 J3.2 J10.1 Q1.4 Q2.4 Q3.4 R25.1 R26.1 R27.1 R55.2 TP14.1 U1.5 | length 2451.3
  Top Layer w7.87: U1.5@2069.8,1710.13 2112.4,1710.13 2147.58,1674.94 2176.89,1674.94 C7.1@2197,1654.83
  Top Layer w20: v1(3020.14,2084) 3026.5,2077.64 R55.2@3026.5,2035
  Power Layer w100: 2357,1624 2536.77,1803.77 2749.43,1803.77 3020.14,2074.48 v1(3020.14,2084) 3299,2362.86 3299,3358.84
  other v1: 2308,1566 2408,1566 408,3166 1408,3166 1508,3166 2508,3166 358,3266 458,3266 558,3266 658,3266 1458,3266 1558,3266 1658,3266 1758,3266 2458,3266 2558,3266 2658,3266 2758,3266 3258,3266 3358,3266 2480,3355 2530,3355 2580,3355 2630,3355 2680,3355 2730,3355 3208,3366 3308,3366 2479.88,3404.96 2529.88,3404.96 2579.88,3404.96 2629.88,3404.96 2679.88,3404.96 2729.88,3404.96 2479.88,3454.96 2529.88,3454.96 2579.88,3454.96 2629.88,3454.96 2679.88,3454.96 2729.88,3454.96 3258,3466 3358,3466 2479.88,3504.96 2529.88,3504.96 2579.88,3504.96 2629.88,3504.96 2679.88,3504.96 2729.88,3504.96 2479.88,3554.96 2529.88,3554.96 2579.88,3554.96 2629.88,3554.96 2679.88,3554.96 2729.88,3554.96 208,3566 308,3566 1308,3566 2308,3566 2408,3566 3208,3566 258,3666 358,3666 458,3666 558,3666 1558,3666 1658,3666 2358,3666 2458,3666 2558,3666 2658,3666 3258,3666 3358,3666 208,3766 308,3766 408,3766 508,3766 608,3766 708,3766 808,3766 908,3766 1008,3766 1608,3766 1708,3766 1808,3766 2408,3766 2508,3766 2608,3766 2708,3766 3308,3766 3180,3860.14 3230,3860.14 3280,3860.14 3330,3860.14 258,3866 358,3866 458,3866 558,3866 658,3866 758,3866 858,3866 958,3866 1058,3866 3358,3866 3130,3910.14 3180,3910.14 3230,3910.14 3280,3910.14 3330,3910.14 3080,3960.14 3130,3960.14 3180,3960.14 3330,3960.14 408,3966 508,3966 608,3966 1108,3966 3208,3966 3080,4010.14 3130,4010.14 3180,4010.14 3330,4010.14 3080,4060.14 3130,4060.14 3180,4060.14 3230,4060.14 3280,4060.14 3330,4060.14 958,4066 1058,4066 1158,4066 1258,4066 2958,4066 3358,4066 3080,4110.14 3130,4110.14 3180,4110.14 3230,4110.14 3280,4110.14 3330,4110.14 1108,4166 1208,4166 1308,4166 1158,4266 1358,4266 1208,4366 1308,4366 1408,4366
  other v2: 1453,3340 1511.41,3340 385,3341 443.41,3341 1566,3341 1626,3341 1684.27,3341 1736,3341 498,3342 558,3342 616.27,3342 668,3342 1454,3394 1735.03,3394 386,3395 667.03,3395 1511.41,3396.6 1566,3397 1626,3396.6 1684.27,3397 443.41,3397.6 498,3398 558,3397.6 616.27,3398 1452,3459.15 384,3460.15 1511.41,3460 1567,3460 1683.84,3460 1735.03,3460 443.41,3461 499,3461 615.84,3461 667.03,3461 1626,3461 558,3462 1626,3513.17 1684.27,3513.17 1736.57,3513 558,3514.17 616.27,3514.17 668.57,3514 1567,3515 499,3516 1512,3518 444,3519 1450.66,3519 382.66,3520 1511.7,3572 1567,3572 1736,3572 443.7,3573 499,3573 668,3573 1450.66,3573 1626,3573 1684.27,3573 382.66,3574 558,3574 616.27,3574
SCL: R4.1 R11.2 U1.30 | length 848.4
  Top Layer w7.87: R4.1@1306,1430.36 1388.88,1513.24 1733.76,1513.24 v1(1734,1513) ; U1.30@1955.63,1623.51 1955.63,1607.96 1951.57,1603.9 1951.57,1578.13 R11.2@1937.29,1563.85 1937.29,1563.71 1967,1534 1968,1535 v1(1969,1535)
  Bottom Layer w7.87: v1(1734,1513) 1740.19,1506.81 1743.03,1506.81 1765.85,1484 1924,1484 1972,1532 v1(1969,1535)
SDA: R2.1 R12.2 U1.29 | length 818.1
  Top Layer w7.87: R2.1@1234,1430.36 1255.21,1430.36 1365.85,1541 v1(1734,1541) ; v1(1832,1517) 1878.85,1563.85 R12.2@1884.29,1563.85 1884.29,1567.92 U1.29@1939.88,1623.51
  Bottom Layer w7.87: v1(1734,1541) 1736.85,1541 1772.85,1505 1820,1505 v1(1832,1517)
SHA: C8.1 J4.3 NT1.1 U1.10 | length 1478.5
  Top Layer w7.87: U1.10@2069.8,1788.87 2089.98,1809.05 2186.59,1809.05 2227.54,1850 2384.38,1850 2433.38,1899 C8.1@2475.44,1899
  Top Layer w25: C8.1@2475.44,1899 2475.44,1905.18 2529.27,1959 2563,1959 J4.3@2634,2030 ; v1(2700,2545) NT1.1@2700,2813.5
  GND Layer w25: J4.3@2634,2030 2700,2096 v1(2700,2545)
SHB: C9.2 J4.7 NT2.1 U1.14 | length 1364.4
  Top Layer w7.87: U1.14@2002.87,1812.49 2002.87,1841.08 2063.92,1902.13 C9.2@2120,1902.13
  Top Layer w25: v1(1703.5,2544.5) 1703.5,2670 1704.76,2671.26 NT2.1@1704.76,2814.33 ; C9.2@2120,1902.13 2120,1920 J4.7@2235,2035
  GND Layer w25: v1(1703.5,2544.5) 2213,2035 J4.7@2235,2035
SHC: C10.2 J4.11 NT3.1 U1.18 | length 1855.3
  Top Layer w7.87: C10.2@1852.44,1901 1852.44,1849.56 1889.51,1812.49 U1.18@1939.88,1812.49
  Top Layer w25: NT3.1@627.77,2802.52 627.77,2743.23 v2(708,2663) ; J4.11@1835,2035 1835,1960 1852.44,1942.56 C10.2@1852.44,1901
  GND Layer w25: v2(708,2663) 1207,2663 J4.11@1835,2035
SN: C31.2 C32.1 R45.1 TP39.1 U1.23 | length 1041.7
  Top Layer w7.87: R45.1@963,1826.44 963,1815 986,1792 1276.73,1792 1320.47,1748.26 1374.41,1748.26 1433.67,1689 TP39.1@1454.87,1689 1576.56,1689 C31.2@1587,1699.44 1666.12,1699.44 C32.1@1667,1698.56 1694.31,1725.87 1739.02,1725.87 1744.88,1731.74 1862.61,1731.74 1868.47,1725.87 U1.23@1920.2,1725.87
SP: C30.2 C31.1 R43.1 TP11.1 U1.22 | length 996.4
  Top Layer w7.87: R43.1@1020,1826.44 1034.29,1826.44 1047.73,1813 1278,1813 1326.99,1764.01 1373.11,1764.01 1419.1,1810 TP11.1@1454.87,1810 1531.56,1810 C31.1@1587,1754.56 1645.12,1754.56 C30.2@1667,1776.44 1701.82,1741.62 1732.49,1741.62 1738.36,1747.49 1869.13,1747.49 1875,1741.62 U1.22@1920.2,1741.62
SPEED/WAKE: J9.25 R51.2 U1.27 | length 1013.2
  Top Layer w7.87: J9.25@1439,1161 J9.25@1436,1158 1442.5,1158 R51.2@1596.5,1312 ; v1(1872,1637) 1897.88,1662.88 U1.27@1920.2,1662.88
  Bottom Layer w7.87: J9.25@1436,1158 1439,1161 1439,1317 1685,1563 1798,1563 v1(1872,1637)
SPEED_IN: J13.1 J13.3 J13.5 SW1.1 | length 502.4
  Top Layer w10: SW1.1@1111,478 1224.21,478 J13.5@1347,600.79 J13.3@1447,600.79 ; J13.3@1436,611.79 J13.3@1447,600.79 ; J13.1@1547,600.79 J13.3@1447,600.79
